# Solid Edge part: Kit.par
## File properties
Dokumentum tartalom típus: 0
Last saved by: psaghy
Revision: 78
Sűrűség: 0,000 kg/m^3
Pontosság: 0,990
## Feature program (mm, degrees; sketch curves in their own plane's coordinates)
base feature "unnamed BaseFeature 1"
sketch for "Furat_1" plane through (0, 0, 32.5) normal (0, 0, 1) x-axis (0, -1, 0)
  hole centre (-16.25, 16.25) bore radius 2.4585
hole "Furat_1" nominal diameter 6 finite  VBottomAngle = 118 deg
sketch for "unnamed Hole 1" plane through (0, 0, 32.5) normal (0, 0, 1) x-axis (0, -1, 0)
  hole centre (-16.25, -16.25) bore radius 2.4585
hole "unnamed Hole 1" finite
sketch for "unnamed Hole 2" plane through (0, 0, 32.5) normal (0, 0, 1) x-axis (0, -1, 0)
  hole centre (16.25, -16.25) bore radius 2.4585
hole "unnamed Hole 2" finite
sketch for "unnamed Hole 3" plane through (0, 0, 32.5) normal (0, 0, 1) x-axis (0, -1, 0)
  hole centre (16.25, 16.25) bore radius 2.4585
hole "unnamed Hole 3" finite
pattern "Hole_1" of "Furat_1", "unnamed Hole 1", "unnamed Hole 2", "unnamed Hole 3"
sketch for "Furat_5" plane through (23.5, 0.0133, 16.7488) normal (1, 0, 0) x-axis (0, 0, -1)
hole "Furat_5" diameter 9.728 finite  ThreadDepth = 9 mm
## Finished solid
Body 1: solid body, 384 faces, 920 edges, 589 vertices, 3 internal voids.
  Faces by surface: cylinder 131, plane 125, cone 46, torus 39, spline 31, sphere 10, swept 2
  Edges by curve: circle 312, curve on surface 296, line 296, spline 16
Bounding box of the edges (mm; curved faces can reach further): 47.001 x 47.000 x 44.500, from (-23.5, -23.5, 6) to (23.5005, 23.5, 50.5).
Cylindrical faces by radius (mm): R0.2287 x1, R0.2297 x1, R0.2305 x1, R0.232 x1, R0.2354 x1, R0.2616 x1, R0.2684 x1, R0.2696 x1, R0.274 x1, R0.2809 x1, R0.2869 x1, R0.2897 x2, R0.2949 x1, R0.2975 x1, R0.2999 x1, R0.3047 x1, R0.3049 x1, R0.3054 x1, R0.3191 x1, R0.3251 x1, R0.3471 x1, R0.361 x1, R0.3789 x1, R0.3925 x1, R0.3994 x1, R0.4078 x1, R0.4206 x1, R0.4339 x1, R0.4364 x1, R0.4536 x1, R0.4559 x1, R0.4564 x1, R0.4771 x1, R0.4781 x1, R0.5 x7, R0.5094 x1, R0.5174 x1, R0.5354 x1, R0.5534 x1, R0.6836 x1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
Conical faces (half-angle, radius in mm at the cone's reference point): 1.6538 deg R7.75 x1, 3.5477 deg R8.7454 x1, 5.1549 deg R0.4847 x1, 5.762 deg R6.4 x1, 11.1239 deg R6.0056 x1, 15 deg R13.6406 x1, 15.3654 deg R6.7214 x1, 19.3654 deg R7.1921 x1, 25.0169 deg R10.31 x1, 27.5528 deg R20.5 x4, 30 deg R4.0866 x1, 30 deg R7.8557 x2, 30 deg R8.1443 x1, 30 deg R14.5 x1, 45 deg R1.1 x1, 45 deg R2.3 x1, 45 deg R2.4 x1, 45 deg R3.25 x8, 45 deg R4.85 x8, 45 deg R5.18 x1, 45 deg R6.15 x2, 45 deg R11.25 x1, 59 deg R1.75 x1, 59 deg R2.4585 x4
Toroidal faces (ring radius, tube radius in mm): R0.7228 r0.5 x1, R0.8364 r0.5 x1, R1.4663 r0.5006 x3, R3.3 r0.3 x4, R3.6 r0.4 x1, R3.7 r0.3 x1, R4.95 r0.2 x4, R5.65 r0.5 x4, R6.3 r0.3 x1, R6.3085 r0.3 x1, R7.4279 r0.25 x1, R7.75 r0.5 x1, R8 r0.5 x1, R8.2464 r0.5 x1, R10.8 r0.2 x1, R12 r2 x1, R12.8663 r0.5 x1, R15.5 r0.5 x1, R18 r1 x3, R22.5 r1 x6, R23.8031 r0.5 x1
Spherical faces by radius (mm): R0.5 x4, R1 x6
Planar faces by outward normal: +x 19, +y 9, +z 29, -x 2, -y 9, -z 17, oblique 40
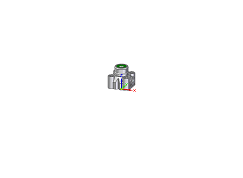
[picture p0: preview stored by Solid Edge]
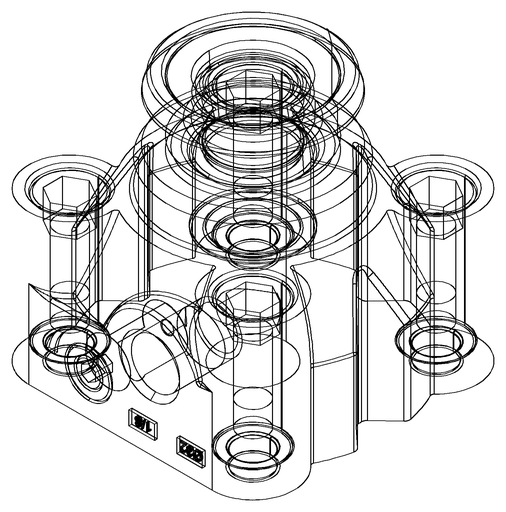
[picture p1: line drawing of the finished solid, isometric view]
